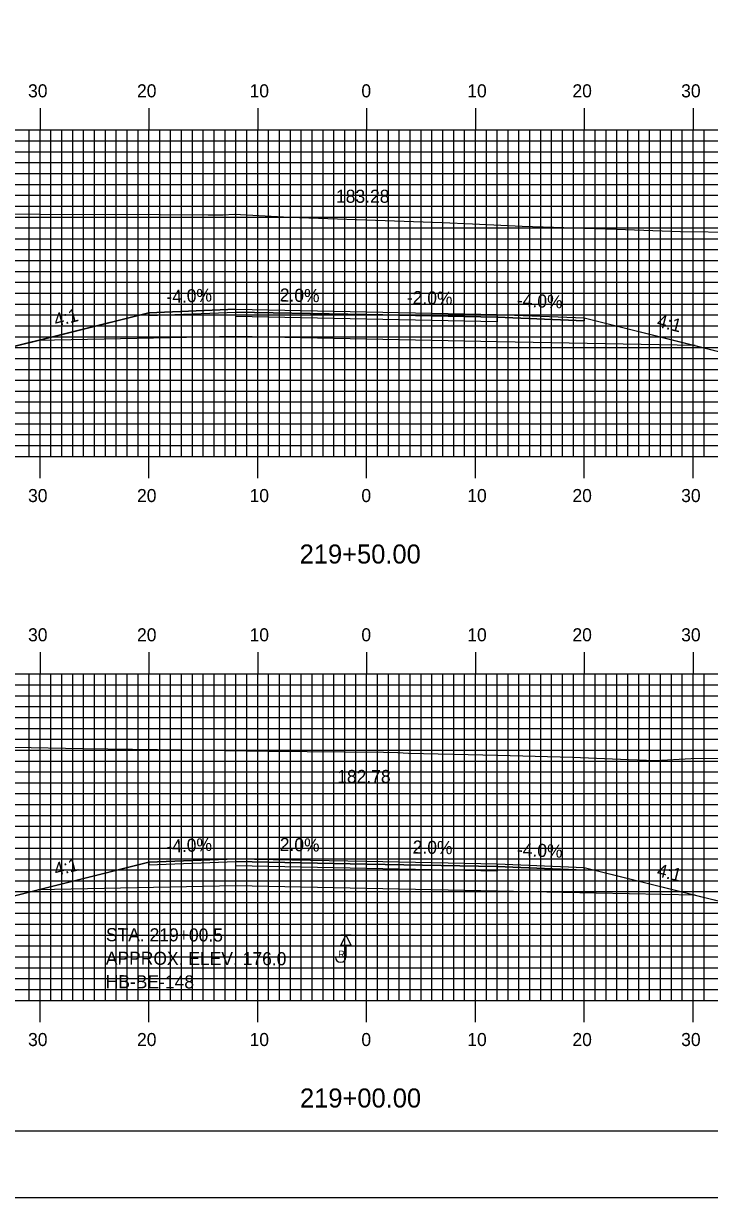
# Model space of a CAD drawing. Extents: x 1797207 to 1797550, y 442591 to 442811.
# Drawn here: x 1797341.4 to 1797404.4, y 442590.5 to 442698.5 of the extents above; entities that cross this region are included whole.
import ezdxf

# ---------------------------------------------------------------- set-up
doc = ezdxf.new("R2010")
doc.units = 0
for name, color, linetype in [('ANNOTATION', 7, 'Continuous'), ('BORDER', 7, 'Continuous'), ('BORING - REFUSAL', 7, 'Continuous'), ('D_Roadway_Centerline', 7, 'Continuous'), ('D_Roadway_Centerline_Text', 7, 'Continuous'), ('D_Roadway_Edge_Shoulder', 7, 'Continuous'), ('D_Roadway_Edge_TW', 7, 'Continuous'), ('D_Roadway_Pavement', 7, 'Continuous'), ('D_Roadway_SlopeLines', 7, 'Continuous'), ('D_Roadway_SubGrade', 7, 'Continuous'), ('H_V ANNOTATION', 7, 'Continuous'), ('MAJOR', 7, 'Continuous'), ('MINOR', 7, 'Continuous'), ('PLOT BOUNDARY', 7, 'Continuous'), ('S_Roadway_Centerline', 7, 'Continuous')]:
    doc.layers.add(name, color=color, linetype=linetype)

msp = doc.modelspace()

# ---------------------------------------------------------------- linework, layer by layer
at = {"layer": 'BORDER'}
msp.add_lwpolyline([(1797223.33, 442596.67), (1797543.33, 442596.67), (1797543.33, 442806.67), (1797223.33, 442806.67)], close=True, dxfattribs=at)
at = {"layer": 'BORING - REFUSAL'}
for p, q in [((1797371.51, 442614.67), (1797370.55, 442614.67)), ((1797371.03, 442613.71), (1797371.03, 442612.65))]:
    msp.add_line(p, q, dxfattribs=at)
msp.add_lwpolyline([(1797371.03, 442614.67), (1797371.51, 442613.71), (1797370.55, 442613.71)], close=True, dxfattribs=at)
msp.add_arc((1797370.55, 442612.65), 0.485, 180, 0, dxfattribs=at)
at = {"layer": 'D_Roadway_Centerline'}
for points in [[(1797282.93, 442682.01), (1797284.18, 442681.93), (1797285.43, 442681.68), (1797286.68, 442681.29), (1797287.93, 442680.74), (1797305.44, 442671.99), (1797317.5, 442671.87), (1797338.76, 442668.33), (1797342.76, 442669.33), (1797352.93, 442671.87), (1797360.93, 442672.19), (1797372.93, 442671.95), (1797384.93, 442671.71), (1797392.93, 442671.39), (1797403.11, 442668.85), (1797407.11, 442667.85), (1797428.37, 442671.39), (1797448.91, 442671.59), (1797457.93, 442676.11), (1797459.18, 442676.65), (1797460.43, 442677.04), (1797461.68, 442677.28), (1797462.93, 442677.35)], [(1797282.93, 442632.85), (1797284.18, 442632.77), (1797285.43, 442632.53), (1797286.68, 442632.14), (1797287.93, 442631.59), (1797308.19, 442621.46), (1797317.5, 442621.37), (1797338.76, 442617.83), (1797342.76, 442618.83), (1797352.93, 442621.37), (1797360.93, 442621.69), (1797372.93, 442621.45), (1797384.93, 442621.21), (1797392.93, 442620.89), (1797403.11, 442618.35), (1797407.11, 442617.35), (1797428.37, 442620.89), (1797445.43, 442621.06), (1797457.93, 442627.31), (1797459.18, 442627.85), (1797460.43, 442628.22), (1797461.68, 442628.41), (1797462.93, 442628.43)]]:
    msp.add_lwpolyline(points, dxfattribs=at)
at = {"layer": 'D_Roadway_Edge_Shoulder'}
for points in [[(1797360.93, 442672.19), (1797352.93, 442671.87), (1797352.93, 442671.62), (1797360.93, 442671.94)], [(1797384.93, 442671.71), (1797392.93, 442671.39), (1797392.93, 442671.14), (1797384.93, 442671.46)], [(1797360.93, 442621.69), (1797352.93, 442621.37), (1797352.93, 442621.12), (1797360.93, 442621.44)], [(1797384.93, 442621.21), (1797392.93, 442620.89), (1797392.93, 442620.64), (1797384.93, 442620.96)]]:
    msp.add_lwpolyline(points, close=True, dxfattribs=at)
at = {"layer": 'D_Roadway_Edge_TW'}
for points in [[(1797360.93, 442671.94), (1797360.93, 442672.19), (1797372.93, 442671.95), (1797384.93, 442671.71), (1797384.93, 442671.46), (1797372.93, 442671.7)], [(1797360.93, 442621.44), (1797360.93, 442621.69), (1797372.93, 442621.45), (1797384.93, 442621.21), (1797384.93, 442620.96), (1797372.93, 442621.2)]]:
    msp.add_lwpolyline(points, close=True, dxfattribs=at)
at = {"layer": 'D_Roadway_Pavement'}
for points in [[(1797360.93, 442671.52), (1797360.93, 442671.94), (1797372.93, 442671.7), (1797384.93, 442671.46), (1797384.93, 442671.04), (1797372.93, 442671.28)], [(1797360.93, 442621.02), (1797360.93, 442621.44), (1797372.93, 442621.2), (1797384.93, 442620.96), (1797384.93, 442620.54), (1797372.93, 442620.78)]]:
    msp.add_lwpolyline(points, close=True, dxfattribs=at)
at = {"layer": 'D_Roadway_SlopeLines'}
for points in [[(1797352.93, 442671.87), (1797338.76, 442668.33)], [(1797392.93, 442671.39), (1797407.11, 442667.85)], [(1797352.93, 442621.37), (1797338.76, 442617.83)], [(1797392.93, 442620.89), (1797407.11, 442617.35)]]:
    msp.add_lwpolyline(points, dxfattribs=at)
at = {"layer": 'D_Roadway_SubGrade'}
for points in [[(1797360.93, 442669.69), (1797342.76, 442669.33), (1797352.93, 442671.87), (1797352.93, 442671.62), (1797360.93, 442671.94), (1797372.93, 442671.7), (1797384.93, 442671.46), (1797392.93, 442671.14), (1797392.93, 442671.39), (1797403.11, 442668.85), (1797384.93, 442669.21), (1797372.93, 442669.45)], [(1797360.93, 442619.19), (1797342.76, 442618.83), (1797352.93, 442621.37), (1797352.93, 442621.12), (1797360.93, 442621.44), (1797372.93, 442621.2), (1797384.93, 442620.96), (1797392.93, 442620.64), (1797392.93, 442620.89), (1797403.11, 442618.35), (1797384.93, 442618.71), (1797372.93, 442618.95)]]:
    msp.add_lwpolyline(points, close=True, dxfattribs=at)
at = {"layer": 'MAJOR'}
for p, q in [((1797342.93, 442690.67), (1797342.93, 442688.67)), ((1797352.93, 442690.67), (1797352.93, 442688.67)), ((1797362.93, 442690.67), (1797362.93, 442688.67)), ((1797372.93, 442690.67), (1797372.93, 442688.67)), ((1797382.93, 442690.67), (1797382.93, 442688.67)), ((1797392.93, 442690.67), (1797392.93, 442688.67)), ((1797402.93, 442690.67), (1797402.93, 442688.67)), ((1797232.93, 442688.67), (1797512.93, 442688.67)), ((1797232.93, 442688.67), (1797512.93, 442688.67)), ((1797342.93, 442658.67), (1797342.93, 442688.67)), ((1797352.93, 442658.67), (1797352.93, 442688.67)), ((1797362.93, 442658.67), (1797362.93, 442688.67)), ((1797372.93, 442658.67), (1797372.93, 442688.67)), ((1797382.93, 442658.67), (1797382.93, 442688.67)), ((1797392.93, 442658.67), (1797392.93, 442688.67)), ((1797402.93, 442658.67), (1797402.93, 442688.67)), ((1797232.93, 442683.67), (1797512.93, 442683.67)), ((1797232.93, 442678.67), (1797512.93, 442678.67)), ((1797232.93, 442673.67), (1797512.93, 442673.67)), ((1797232.93, 442668.67), (1797512.93, 442668.67)), ((1797232.93, 442663.67), (1797512.93, 442663.67)), ((1797232.93, 442658.67), (1797512.93, 442658.67)), ((1797232.93, 442658.67), (1797512.93, 442658.67)), ((1797342.93, 442656.66), (1797342.93, 442658.67)), ((1797352.93, 442656.66), (1797352.93, 442658.67)), ((1797362.93, 442656.66), (1797362.93, 442658.67)), ((1797372.93, 442656.66), (1797372.93, 442658.67)), ((1797382.93, 442656.66), (1797382.93, 442658.67)), ((1797392.93, 442656.66), (1797392.93, 442658.67)), ((1797402.93, 442656.66), (1797402.93, 442658.67)), ((1797342.93, 442640.67), (1797342.93, 442638.67)), ((1797352.93, 442640.67), (1797352.93, 442638.67)), ((1797362.93, 442640.67), (1797362.93, 442638.67)), ((1797372.93, 442640.67), (1797372.93, 442638.67)), ((1797382.93, 442640.67), (1797382.93, 442638.67)), ((1797392.93, 442640.67), (1797392.93, 442638.67)), ((1797402.93, 442640.67), (1797402.93, 442638.67)), ((1797232.93, 442638.67), (1797512.93, 442638.67)), ((1797232.93, 442638.67), (1797512.93, 442638.67)), ((1797342.93, 442608.67), (1797342.93, 442638.67)), ((1797352.93, 442608.67), (1797352.93, 442638.67)), ((1797362.93, 442608.67), (1797362.93, 442638.67)), ((1797372.93, 442608.67), (1797372.93, 442638.67)), ((1797382.93, 442608.67), (1797382.93, 442638.67)), ((1797392.93, 442608.67), (1797392.93, 442638.67)), ((1797402.93, 442608.67), (1797402.93, 442638.67)), ((1797232.93, 442633.67), (1797512.93, 442633.67)), ((1797232.93, 442628.67), (1797512.93, 442628.67)), ((1797232.93, 442623.67), (1797512.93, 442623.67)), ((1797232.93, 442618.67), (1797512.93, 442618.67)), ((1797232.93, 442613.67), (1797512.93, 442613.67)), ((1797232.93, 442608.67), (1797512.93, 442608.67)), ((1797232.93, 442608.67), (1797512.93, 442608.67)), ((1797342.93, 442606.66), (1797342.93, 442608.67)), ((1797352.93, 442606.66), (1797352.93, 442608.67)), ((1797362.93, 442606.66), (1797362.93, 442608.67)), ((1797372.93, 442606.66), (1797372.93, 442608.67)), ((1797382.93, 442606.66), (1797382.93, 442608.67)), ((1797392.93, 442606.66), (1797392.93, 442608.67)), ((1797402.93, 442606.66), (1797402.93, 442608.67))]:
    msp.add_line(p, q, dxfattribs=at)
at = {"layer": 'MINOR'}
for p, q in [((1797341.93, 442658.67), (1797341.93, 442688.67)), ((1797343.93, 442658.67), (1797343.93, 442688.67)), ((1797344.93, 442658.67), (1797344.93, 442688.67)), ((1797345.93, 442658.67), (1797345.93, 442688.67)), ((1797346.93, 442658.67), (1797346.93, 442688.67)), ((1797347.93, 442658.67), (1797347.93, 442688.67)), ((1797348.93, 442658.67), (1797348.93, 442688.67)), ((1797349.93, 442658.67), (1797349.93, 442688.67)), ((1797350.93, 442658.67), (1797350.93, 442688.67)), ((1797351.93, 442658.67), (1797351.93, 442688.67)), ((1797353.93, 442658.67), (1797353.93, 442688.67)), ((1797354.93, 442658.67), (1797354.93, 442688.67)), ((1797355.93, 442658.67), (1797355.93, 442688.67)), ((1797356.93, 442658.67), (1797356.93, 442688.67)), ((1797357.93, 442658.67), (1797357.93, 442688.67)), ((1797358.93, 442658.67), (1797358.93, 442688.67)), ((1797359.93, 442658.67), (1797359.93, 442688.67)), ((1797360.93, 442658.67), (1797360.93, 442688.67)), ((1797361.93, 442658.67), (1797361.93, 442688.67)), ((1797363.93, 442658.67), (1797363.93, 442688.67)), ((1797364.93, 442658.67), (1797364.93, 442688.67)), ((1797365.93, 442658.67), (1797365.93, 442688.67)), ((1797366.93, 442658.67), (1797366.93, 442688.67)), ((1797367.93, 442658.67), (1797367.93, 442688.67)), ((1797368.93, 442658.67), (1797368.93, 442688.67)), ((1797369.93, 442658.67), (1797369.93, 442688.67)), ((1797370.93, 442658.67), (1797370.93, 442688.67)), ((1797371.93, 442658.67), (1797371.93, 442688.67)), ((1797373.93, 442658.67), (1797373.93, 442688.67)), ((1797374.93, 442658.67), (1797374.93, 442688.67)), ((1797375.93, 442658.67), (1797375.93, 442688.67)), ((1797376.93, 442658.67), (1797376.93, 442688.67)), ((1797377.93, 442658.67), (1797377.93, 442688.67)), ((1797378.93, 442658.67), (1797378.93, 442688.67)), ((1797379.93, 442658.67), (1797379.93, 442688.67)), ((1797380.93, 442658.67), (1797380.93, 442688.67)), ((1797381.93, 442658.67), (1797381.93, 442688.67)), ((1797383.93, 442658.67), (1797383.93, 442688.67)), ((1797384.93, 442658.67), (1797384.93, 442688.67)), ((1797385.93, 442658.67), (1797385.93, 442688.67)), ((1797386.93, 442658.67), (1797386.93, 442688.67)), ((1797387.93, 442658.67), (1797387.93, 442688.67)), ((1797388.93, 442658.67), (1797388.93, 442688.67)), ((1797389.93, 442658.67), (1797389.93, 442688.67)), ((1797390.93, 442658.67), (1797390.93, 442688.67)), ((1797391.93, 442658.67), (1797391.93, 442688.67)), ((1797393.93, 442658.67), (1797393.93, 442688.67)), ((1797394.93, 442658.67), (1797394.93, 442688.67)), ((1797395.93, 442658.67), (1797395.93, 442688.67)), ((1797396.93, 442658.67), (1797396.93, 442688.67)), ((1797397.93, 442658.67), (1797397.93, 442688.67)), ((1797398.93, 442658.67), (1797398.93, 442688.67)), ((1797399.93, 442658.67), (1797399.93, 442688.67)), ((1797400.93, 442658.67), (1797400.93, 442688.67)), ((1797401.93, 442658.67), (1797401.93, 442688.67)), ((1797403.93, 442658.67), (1797403.93, 442688.67)), ((1797232.93, 442687.67), (1797512.93, 442687.67)), ((1797232.93, 442686.67), (1797512.93, 442686.67)), ((1797232.93, 442685.67), (1797512.93, 442685.67)), ((1797232.93, 442684.67), (1797512.93, 442684.67)), ((1797232.93, 442682.67), (1797512.93, 442682.67)), ((1797232.93, 442681.67), (1797512.93, 442681.67)), ((1797232.93, 442680.67), (1797512.93, 442680.67)), ((1797232.93, 442679.67), (1797512.93, 442679.67)), ((1797232.93, 442677.67), (1797512.93, 442677.67)), ((1797232.93, 442676.67), (1797512.93, 442676.67)), ((1797232.93, 442675.67), (1797512.93, 442675.67)), ((1797232.93, 442674.67), (1797512.93, 442674.67)), ((1797232.93, 442672.67), (1797512.93, 442672.67)), ((1797232.93, 442671.67), (1797512.93, 442671.67)), ((1797232.93, 442670.67), (1797512.93, 442670.67)), ((1797232.93, 442669.67), (1797512.93, 442669.67)), ((1797232.93, 442667.67), (1797512.93, 442667.67)), ((1797232.93, 442666.67), (1797512.93, 442666.67)), ((1797232.93, 442665.67), (1797512.93, 442665.67)), ((1797232.93, 442664.67), (1797512.93, 442664.67)), ((1797232.93, 442662.67), (1797512.93, 442662.67)), ((1797232.93, 442661.67), (1797512.93, 442661.67)), ((1797232.93, 442660.67), (1797512.93, 442660.67)), ((1797232.93, 442659.67), (1797512.93, 442659.67)), ((1797341.93, 442608.67), (1797341.93, 442638.67)), ((1797343.93, 442608.67), (1797343.93, 442638.67)), ((1797344.93, 442608.67), (1797344.93, 442638.67)), ((1797345.93, 442608.67), (1797345.93, 442638.67)), ((1797346.93, 442608.67), (1797346.93, 442638.67)), ((1797347.93, 442608.67), (1797347.93, 442638.67)), ((1797348.93, 442608.67), (1797348.93, 442638.67)), ((1797349.93, 442608.67), (1797349.93, 442638.67)), ((1797350.93, 442608.67), (1797350.93, 442638.67)), ((1797351.93, 442608.67), (1797351.93, 442638.67)), ((1797353.93, 442608.67), (1797353.93, 442638.67)), ((1797354.93, 442608.67), (1797354.93, 442638.67)), ((1797355.93, 442608.67), (1797355.93, 442638.67)), ((1797356.93, 442608.67), (1797356.93, 442638.67)), ((1797357.93, 442608.67), (1797357.93, 442638.67)), ((1797358.93, 442608.67), (1797358.93, 442638.67)), ((1797359.93, 442608.67), (1797359.93, 442638.67)), ((1797360.93, 442608.67), (1797360.93, 442638.67)), ((1797361.93, 442608.67), (1797361.93, 442638.67)), ((1797363.93, 442608.67), (1797363.93, 442638.67)), ((1797364.93, 442608.67), (1797364.93, 442638.67)), ((1797365.93, 442608.67), (1797365.93, 442638.67)), ((1797366.93, 442608.67), (1797366.93, 442638.67)), ((1797367.93, 442608.67), (1797367.93, 442638.67)), ((1797368.93, 442608.67), (1797368.93, 442638.67)), ((1797369.93, 442608.67), (1797369.93, 442638.67)), ((1797370.93, 442608.67), (1797370.93, 442638.67)), ((1797371.93, 442608.67), (1797371.93, 442638.67)), ((1797373.93, 442608.67), (1797373.93, 442638.67)), ((1797374.93, 442608.67), (1797374.93, 442638.67)), ((1797375.93, 442608.67), (1797375.93, 442638.67)), ((1797376.93, 442608.67), (1797376.93, 442638.67)), ((1797377.93, 442608.67), (1797377.93, 442638.67)), ((1797378.93, 442608.67), (1797378.93, 442638.67)), ((1797379.93, 442608.67), (1797379.93, 442638.67)), ((1797380.93, 442608.67), (1797380.93, 442638.67)), ((1797381.93, 442608.67), (1797381.93, 442638.67)), ((1797383.93, 442608.67), (1797383.93, 442638.67)), ((1797384.93, 442608.67), (1797384.93, 442638.67)), ((1797385.93, 442608.67), (1797385.93, 442638.67)), ((1797386.93, 442608.67), (1797386.93, 442638.67)), ((1797387.93, 442608.67), (1797387.93, 442638.67)), ((1797388.93, 442608.67), (1797388.93, 442638.67)), ((1797389.93, 442608.67), (1797389.93, 442638.67)), ((1797390.93, 442608.67), (1797390.93, 442638.67)), ((1797391.93, 442608.67), (1797391.93, 442638.67)), ((1797393.93, 442608.67), (1797393.93, 442638.67)), ((1797394.93, 442608.67), (1797394.93, 442638.67)), ((1797395.93, 442608.67), (1797395.93, 442638.67)), ((1797396.93, 442608.67), (1797396.93, 442638.67)), ((1797397.93, 442608.67), (1797397.93, 442638.67)), ((1797398.93, 442608.67), (1797398.93, 442638.67)), ((1797399.93, 442608.67), (1797399.93, 442638.67)), ((1797400.93, 442608.67), (1797400.93, 442638.67)), ((1797401.93, 442608.67), (1797401.93, 442638.67)), ((1797403.93, 442608.67), (1797403.93, 442638.67)), ((1797232.93, 442637.67), (1797512.93, 442637.67)), ((1797232.93, 442636.67), (1797512.93, 442636.67)), ((1797232.93, 442635.67), (1797512.93, 442635.67)), ((1797232.93, 442634.67), (1797512.93, 442634.67)), ((1797232.93, 442632.67), (1797512.93, 442632.67)), ((1797232.93, 442631.67), (1797512.93, 442631.67)), ((1797232.93, 442630.67), (1797512.93, 442630.67)), ((1797232.93, 442629.67), (1797512.93, 442629.67)), ((1797232.93, 442627.67), (1797512.93, 442627.67)), ((1797232.93, 442626.67), (1797512.93, 442626.67)), ((1797232.93, 442625.67), (1797512.93, 442625.67)), ((1797232.93, 442624.67), (1797512.93, 442624.67)), ((1797232.93, 442622.67), (1797512.93, 442622.67)), ((1797232.93, 442621.67), (1797512.93, 442621.67)), ((1797232.93, 442620.67), (1797512.93, 442620.67)), ((1797232.93, 442619.67), (1797512.93, 442619.67)), ((1797232.93, 442617.67), (1797512.93, 442617.67)), ((1797232.93, 442616.67), (1797512.93, 442616.67)), ((1797232.93, 442615.67), (1797512.93, 442615.67)), ((1797232.93, 442614.67), (1797512.93, 442614.67)), ((1797232.93, 442612.67), (1797512.93, 442612.67)), ((1797232.93, 442611.67), (1797512.93, 442611.67)), ((1797232.93, 442610.67), (1797512.93, 442610.67)), ((1797232.93, 442609.67), (1797512.93, 442609.67))]:
    msp.add_line(p, q, dxfattribs=at)
at = {"layer": 'PLOT BOUNDARY'}
msp.add_lwpolyline([(1797207.14, 442590.55), (1797547.14, 442590.55), (1797547.14, 442810.55), (1797207.14, 442810.55)], close=True, dxfattribs=at)
at = {"layer": 'S_Roadway_Centerline'}
for points in [[(1797331.88, 442680.97), (1797354, 442680.91), (1797358.39, 442680.88), (1797359.76, 442680.87), (1797360.75, 442680.94), (1797365.87, 442680.66), (1797379.87, 442680.16), (1797382.65, 442680.04), (1797387.21, 442679.84), (1797395.87, 442679.55), (1797401.77, 442679.34), (1797406.89, 442679.28), (1797413.91, 442678.99), (1797421.16, 442678.73), (1797429.95, 442678.41), (1797441.77, 442677.53), (1797443.31, 442677.47), (1797446.26, 442677.4), (1797461.77, 442677.35), (1797469.61, 442677.36)], [(1797340.53, 442631.94), (1797346.87, 442631.81), (1797356.03, 442631.71), (1797363.94, 442631.57), (1797374.47, 442631.47), (1797375.81, 442631.45), (1797376.78, 442631.38), (1797384.99, 442631.2), (1797391.85, 442631.02), (1797396.99, 442630.8), (1797399.46, 442630.72), (1797402.74, 442630.89), (1797416.89, 442631.01), (1797430.84, 442629.76), (1797434.32, 442629.44), (1797437.34, 442629.3), (1797446.4, 442629.01), (1797458.35, 442628.67), (1797458.5, 442628.66), (1797458.68, 442628.65), (1797478.23, 442627.63)]]:
    msp.add_lwpolyline(points, dxfattribs=at)

# ---------------------------------------------------------------- texts
at = {"layer": 'ANNOTATION'}
for s, rotation, p in [('-4.0%', 2.2906, (1797354.56, 442672.74)), ('2.0%', 358.8542, (1797364.94, 442672.91)), ('-2.0%', 358.8542, (1797376.62, 442672.68)), ('-4.0%', 357.7094, (1797386.72, 442672.44)), ('4:1', 14.0362, (1797344.38, 442670.59)), ('4:1', 345.9638, (1797399.52, 442670.6)), ('-4.0%', 2.2906, (1797354.56, 442622.24)), ('2.0%', 358.8542, (1797364.94, 442622.41)), ('-2.0%', 358.8542, (1797376.62, 442622.18)), ('-4.0%', 357.7094, (1797386.72, 442621.94)), ('4:1', 14.0362, (1797344.38, 442620.09)), ('4:1', 345.9638, (1797399.52, 442620.1))]:
    msp.add_text(s, height=1.2, rotation=rotation, dxfattribs=at).set_placement(p)
at = {"layer": 'BORING - REFUSAL'}
for s, p in [('STA. 219+00.5', (1797348.98, 442614.11)), ('APPROX. ELEV. 176.0', (1797348.97, 442611.95)), ('HB-BE-148', (1797348.96, 442609.79))]:
    msp.add_text(s, height=1.2, rotation=359.8142, dxfattribs=at).set_placement(p)
msp.add_text('R', height=0.64, dxfattribs=at).set_placement((1797370.32, 442612.59))
at = {"layer": 'D_Roadway_Centerline'}
for s, p in [('C', (1797372.93, 442671.95)), ('L', (1797372.93, 442671.94)), ('C', (1797372.93, 442621.45)), ('L', (1797372.93, 442621.44))]:
    msp.add_text(s, height=0.0146, dxfattribs=at).set_placement(p)
at = {"layer": 'D_Roadway_Centerline_Text'}
for s, p in [('183.28', (1797370.12, 442681.98)), ('182.78', (1797370.23, 442628.65))]:
    msp.add_text(s, height=1.2, dxfattribs=at).set_placement(p)
at = {"layer": 'H_V ANNOTATION'}
for s, height, p in [('30', 1.2, (1797341.83, 442691.67)), ('20', 1.2, (1797351.84, 442691.67)), ('10', 1.2, (1797362.18, 442691.67)), ('0', 1.2, (1797372.45, 442691.67)), ('10', 1.2, (1797382.18, 442691.67)), ('20', 1.2, (1797391.84, 442691.67)), ('30', 1.2, (1797401.83, 442691.67)), ('30', 1.2, (1797341.83, 442654.47)), ('20', 1.2, (1797351.84, 442654.47)), ('10', 1.2, (1797362.18, 442654.47)), ('0', 1.2, (1797372.45, 442654.47)), ('10', 1.2, (1797382.18, 442654.47)), ('20', 1.2, (1797391.84, 442654.47)), ('30', 1.2, (1797401.83, 442654.47)), ('219+50.00', 1.75, (1797366.78, 442648.82)), ('30', 1.2, (1797341.83, 442641.67)), ('20', 1.2, (1797351.84, 442641.67)), ('10', 1.2, (1797362.18, 442641.67)), ('0', 1.2, (1797372.45, 442641.67)), ('10', 1.2, (1797382.18, 442641.67)), ('20', 1.2, (1797391.84, 442641.67)), ('30', 1.2, (1797401.83, 442641.67)), ('30', 1.2, (1797341.83, 442604.47)), ('20', 1.2, (1797351.84, 442604.47)), ('10', 1.2, (1797362.18, 442604.47)), ('0', 1.2, (1797372.45, 442604.47)), ('10', 1.2, (1797382.18, 442604.47)), ('20', 1.2, (1797391.84, 442604.47)), ('30', 1.2, (1797401.83, 442604.47)), ('219+00.00', 1.75, (1797366.81, 442598.82))]:
    msp.add_text(s, height=height, dxfattribs=at).set_placement(p)

doc.saveas('drawing.dxf')
